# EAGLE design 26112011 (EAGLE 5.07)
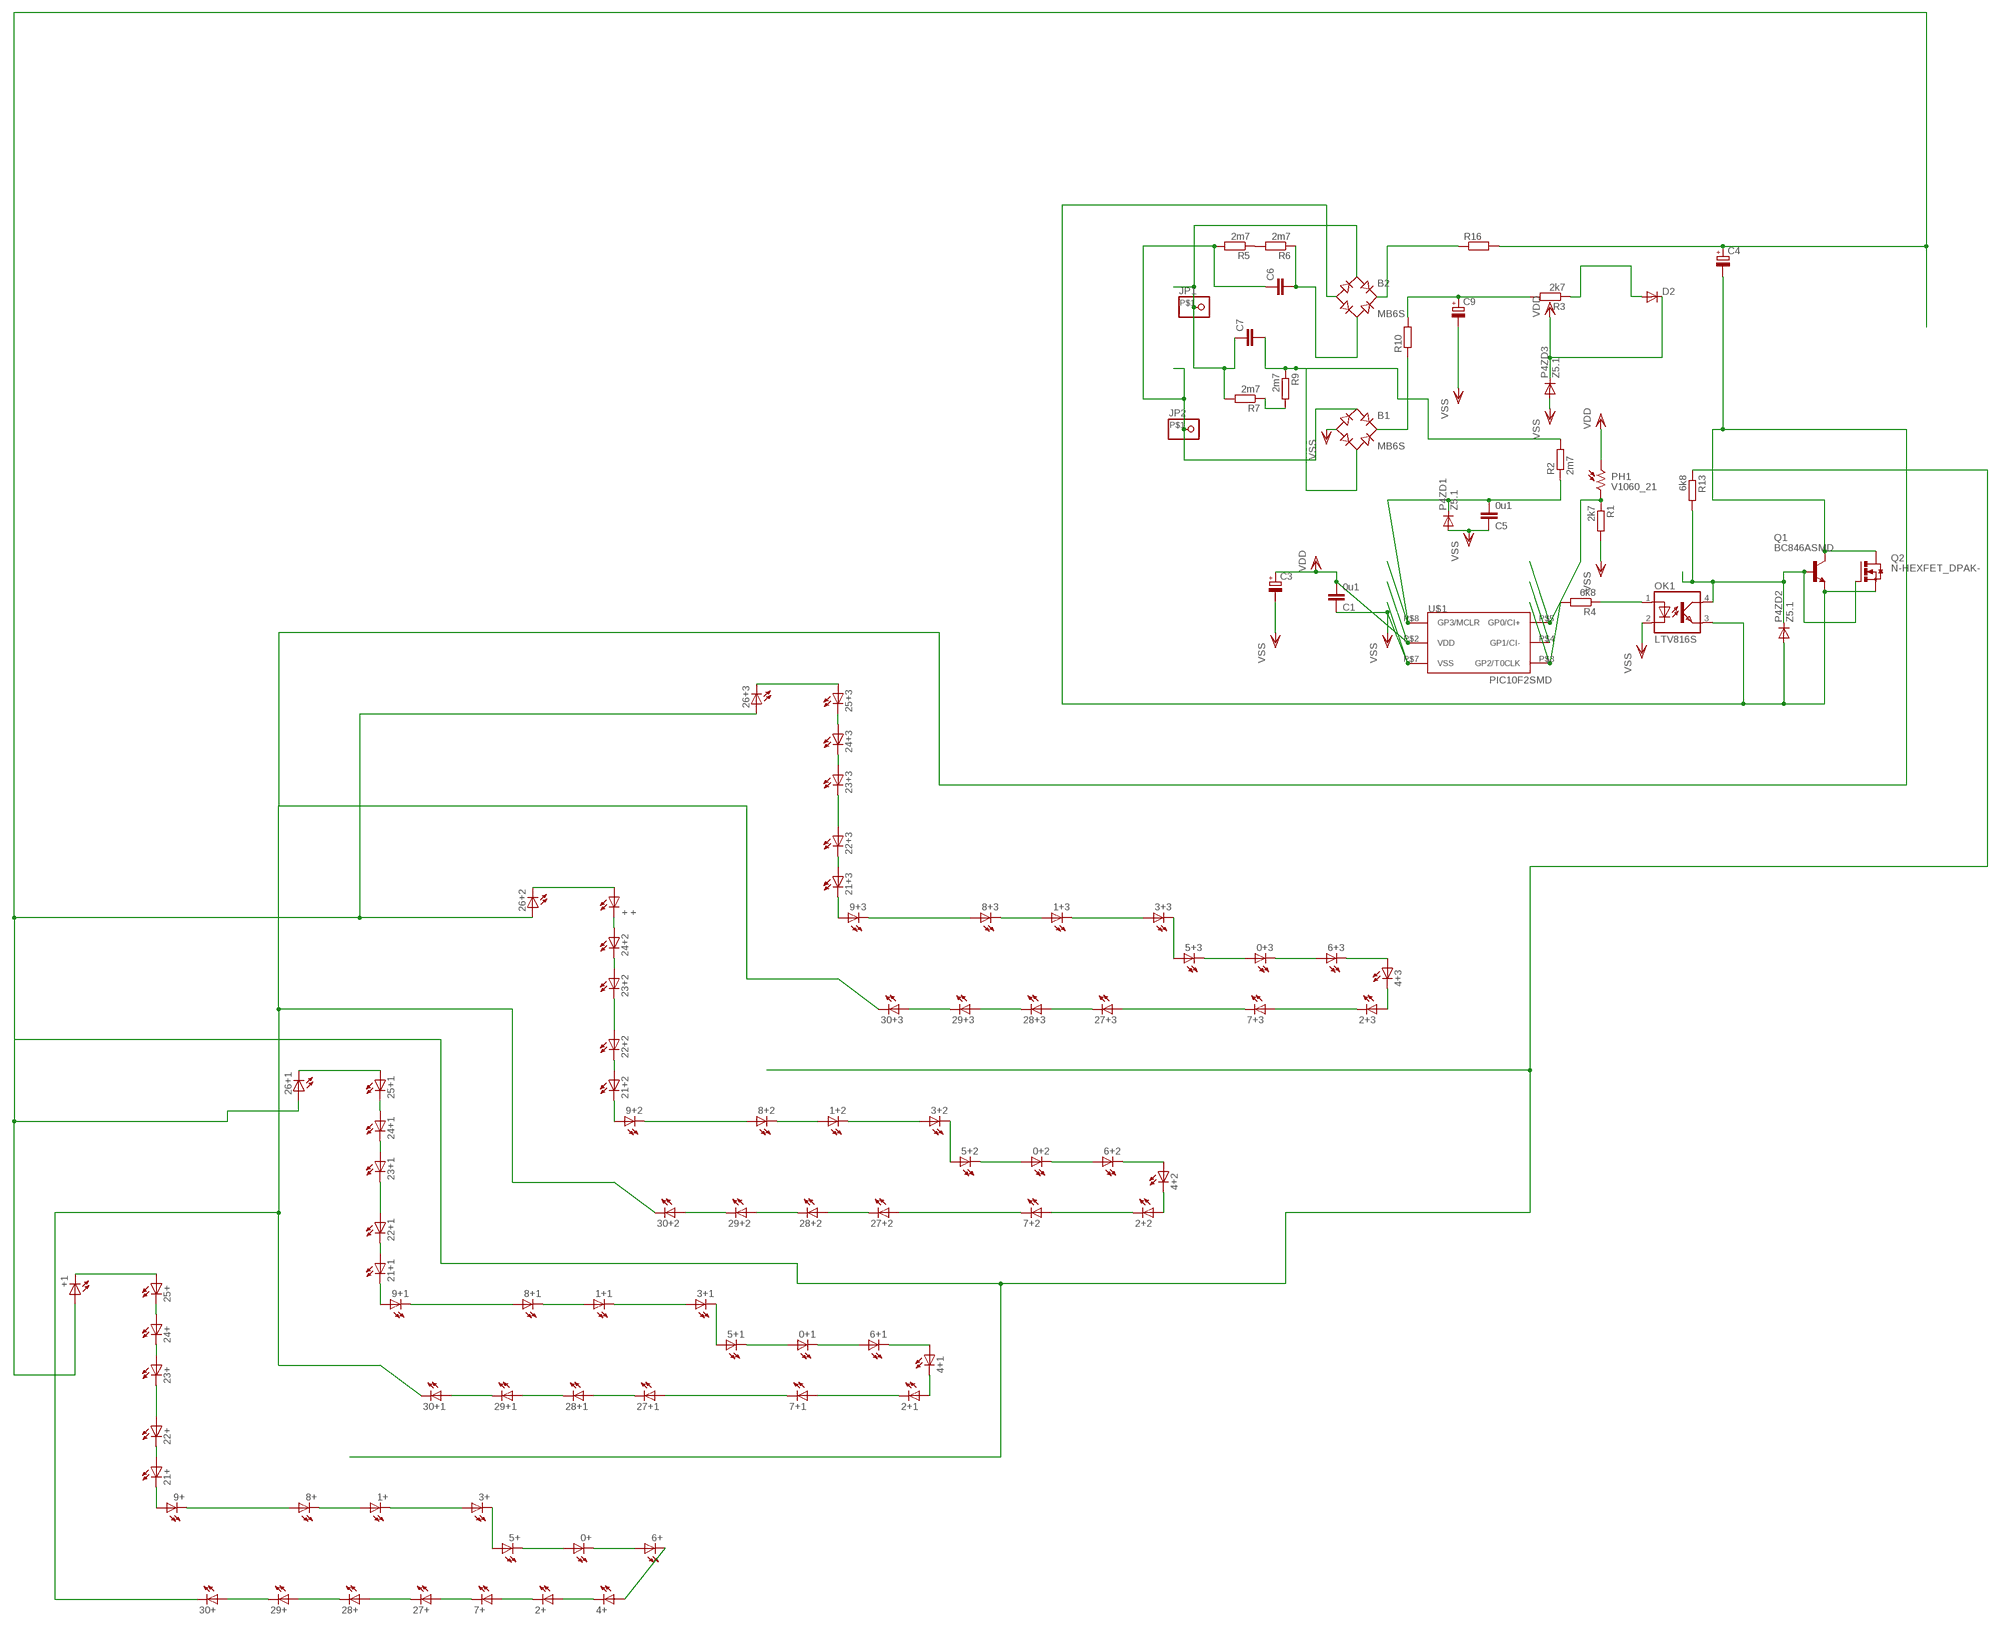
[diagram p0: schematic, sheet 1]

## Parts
0+  LED1210  [1210]
0+1  LED1210  [1210]
0+2  LED1210  [1210]
0+3  LED1210  [1210]
1+  LED1210  [1210]
1+1  LED1210  [1210]
1+2  LED1210  [1210]
1+3  LED1210  [1210]
2+  LED1210  [1210]
2+1  LED1210  [1210]
2+2  LED1210  [1210]
2+3  LED1210  [1210]
3+  LED1210  [1210]
3+1  LED1210  [1210]
3+2  LED1210  [1210]
3+3  LED1210  [1210]
4+  LED1210  [1210]
4+1  LED1210  [1210]
4+2  LED1210  [1210]
4+3  LED1210  [1210]
5+  LED1210  [1210]
5+1  LED1210  [1210]
5+2  LED1210  [1210]
5+3  LED1210  [1210]
6+  LED1210  [1210]
6+1  LED1210  [1210]
6+2  LED1210  [1210]
6+3  LED1210  [1210]
7+  LED1210  [1210]
7+1  LED1210  [1210]
7+2  LED1210  [1210]
7+3  LED1210  [1210]
8+  LED1210  [1210]
8+1  LED1210  [1210]
8+2  LED1210  [1210]
8+3  LED1210  [1210]
9+  LED1210  [1210]
9+1  LED1210  [1210]
9+2  LED1210  [1210]
9+3  LED1210  [1210]
21+  LED1210  [1210]
21+1  LED1210  [1210]
21+2  LED1210  [1210]
21+3  LED1210  [1210]
22+  LED1210  [1210]
22+1  LED1210  [1210]
22+2  LED1210  [1210]
22+3  LED1210  [1210]
23+  LED1210  [1210]
23+1  LED1210  [1210]
23+2  LED1210  [1210]
23+3  LED1210  [1210]
24+  LED1210  [1210]
24+1  LED1210  [1210]
24+2  LED1210  [1210]
24+3  LED1210  [1210]
25+  LED1210  [1210]
25+1  LED1210  [1210]
25+3  LED1210  [1210]
26+1  LED1210  [1210]
26+2  LED1210  [1210]
26+3  LED1210  [1210]
27+  LED1210  [1210]
27+1  LED1210  [1210]
27+2  LED1210  [1210]
27+3  LED1210  [1210]
28+  LED1210  [1210]
28+1  LED1210  [1210]
28+2  LED1210  [1210]
28+3  LED1210  [1210]
29+  LED1210  [1210]
29+1  LED1210  [1210]
29+2  LED1210  [1210]
29+3  LED1210  [1210]
30+  LED1210  [1210]
30+1  LED1210  [1210]
30+2  LED1210  [1210]
30+3  LED1210  [1210]
+  +  LED1210  [1210]
+1  LED1210  [1210]
B1  MB6S  [SOIC-4]
B2  MB6S  [SOIC-4]
C1  0u1  C-EUC1206  [C1206]
C3  CPOL-EUD  [PANASONIC_D]
C4  CPOL-EUSANYO_SMD_F12  [SANYO-OSCON_SMD_F12]
C5  0u1  C-EUC1206  [C1206]
C6  C-EUSMD200  [SMD200]
C7  C-EUSMD100  [SMD100]
C9  CPOL-EUD  [PANASONIC_D]
D2  DIODE-MINIMELF  [MINIMELF]
JP1  PINHD-1X1SMD  [SMD1X1]
JP2  PINHD-1X1SMD  [SMD1X1]
OK1  LTV816S  [SMD4]
P4ZD1  Z5.1  DIODE-MINIMELF  [MINIMELF]
P4ZD2  Z5.1  DIODE-MINIMELF  [MINIMELF]
P4ZD3  Z5.1  DIODE-MINIMELF  [MINIMELF]
PH1  V1060_21  [TO-5_V10]
Q1  BC846ASMD  [SOT23]
Q2  N-HEXFET_DPAK-  [TO252]
R1  2k7  R-EU_R1206  [R1206]
R2  2m7  R-EU_R1206  [R1206]
R3  2k7  R-EU_R1206  [R1206]
R4  6k8  R-EU_R1206  [R1206]
R5  2m7  R-EU_R1210  [R1210]
R6  2m7  R-EU_R1210  [R1210]
R7  2m7  R-EU_R1210  [R1210]
R9  2m7  R-EU_R1210  [R1210]
R10  R-EU_SMD15  [SMDCARB15]
R13  6k8  R-EU_R1206  [R1206]
R16  R-EU_SMD15  [SMDCARB15]
U$1  PIC10F2SMD  [DIL8SMD]

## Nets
AC1: B1.~1(AC1) C6.P$1 JP2.P$1 R5.2
AC2: B2.~1(AC1) C7.P$1 JP1.P$1 R7.2
CBIG: B2.~2(AC2) C6.P$2 R6.1
CSMALL: B1.~2(AC2) C7.P$2 R2.2 R9.1
D+: 26+1.P$1(A) 26+2.P$1(A) 26+3.P$1(A) +1.P$1(A) C4.+ R13.1 R16.P$2
DR+: C9.+ R3.2 R10.P$2
MINUS: 30+1.P$2(C) 30+2.P$2(C) 30+3.P$2(C) 30+.P$2(C) C4.- Q1.3(C) Q2.3(D)
N$6: 8+.P$1(A) 9+.P$2(C)
N$7: 29+.P$2(C) 30+.P$1(A)
N$8: 28+.P$2(C) 29+.P$1(A)
N$9: 27+.P$2(C) 28+.P$1(A)
N$10: 29+1.P$2(C) 30+1.P$1(A)
N$11: 28+1.P$2(C) 29+1.P$1(A)
N$12: 2+.P$2(C) 7+.P$1(A)
N$13: 7+.P$2(C) 27+.P$1(A)
N$14: 2+.P$1(A) 4+.P$2(C)
N$15: 4+.P$1(A) 6+.P$2(C)
N$16: 0+.P$2(C) 6+.P$1(A)
N$17: 0+.P$1(A) 5+.P$2(C)
N$18: 3+.P$2(C) 5+.P$1(A)
N$19: 1+.P$2(C) 3+.P$1(A)
N$20: 1+.P$1(A) 8+.P$2(C)
N$21: 27+1.P$2(C) 28+1.P$1(A)
N$22: 2+1.P$1(A) 4+1.P$2(C)
N$23: 9+.P$1(A) 21+.P$2(C)
N$24: 21+.P$1(A) 22+.P$2(C)
N$25: 22+.P$1(A) 23+.P$2(C)
N$26: 24+.P$1(A) 25+.P$2(C)
N$27: 25+.P$1(A) +1.P$2(C)
N$28: 23+.P$1(A) 24+.P$2(C)
N$29: 4+1.P$1(A) 6+1.P$2(C)
N$30: 0+1.P$2(C) 6+1.P$1(A)
N$31: 0+1.P$1(A) 5+1.P$2(C)
N$32: 3+1.P$2(C) 5+1.P$1(A)
N$33: 1+1.P$2(C) 3+1.P$1(A)
N$34: 1+1.P$1(A) 8+1.P$2(C)
N$35: 9+1.P$1(A) 21+1.P$2(C)
N$36: 21+1.P$1(A) 22+1.P$2(C)
N$37: 22+1.P$1(A) 23+1.P$2(C)
N$38: 25+1.P$1(A) 26+1.P$2(C)
N$39: 24+1.P$1(A) 25+1.P$2(C)
N$40: 23+1.P$1(A) 24+1.P$2(C)
N$41: 2+1.P$2(C) 7+1.P$1(A)
N$42: 7+1.P$2(C) 27+1.P$1(A)
N$43: 8+1.P$1(A) 9+1.P$2(C)
N$46: 29+2.P$2(C) 30+2.P$1(A)
N$47: 28+2.P$2(C) 29+2.P$1(A)
N$48: 27+2.P$2(C) 28+2.P$1(A)
N$49: 2+2.P$1(A) 4+2.P$2(C)
N$50: 4+2.P$1(A) 6+2.P$2(C)
N$51: 0+2.P$2(C) 6+2.P$1(A)
N$52: 0+2.P$1(A) 5+2.P$2(C)
N$53: 3+2.P$2(C) 5+2.P$1(A)
N$54: 1+2.P$2(C) 3+2.P$1(A)
N$55: 1+2.P$1(A) 8+2.P$2(C)
N$56: 9+2.P$1(A) 21+2.P$2(C)
N$57: 21+2.P$1(A) 22+2.P$2(C)
N$58: 22+2.P$1(A) 23+2.P$2(C)
N$59: 26+2.P$2(C) +.P$1(A)
N$60: 24+2.P$1(A) +.P$2(C)
N$61: 23+2.P$1(A) 24+2.P$2(C)
N$62: 2+2.P$2(C) 7+2.P$1(A)
N$63: 7+2.P$2(C) 27+2.P$1(A)
N$64: 8+2.P$1(A) 9+2.P$2(C)
N$67: 29+3.P$2(C) 30+3.P$1(A)
N$68: 28+3.P$2(C) 29+3.P$1(A)
N$69: 27+3.P$2(C) 28+3.P$1(A)
N$70: 2+3.P$1(A) 4+3.P$2(C)
N$71: 4+3.P$1(A) 6+3.P$2(C)
N$72: 0+3.P$2(C) 6+3.P$1(A)
N$73: 0+3.P$1(A) 5+3.P$2(C)
N$74: 3+3.P$2(C) 5+3.P$1(A)
N$75: 1+3.P$2(C) 3+3.P$1(A)
N$76: 1+3.P$1(A) 8+3.P$2(C)
N$77: 9+3.P$1(A) 21+3.P$2(C)
N$78: 21+3.P$1(A) 22+3.P$2(C)
N$79: 22+3.P$1(A) 23+3.P$2(C)
N$80: 25+3.P$1(A) 26+3.P$2(C)
N$81: 24+3.P$1(A) 25+3.P$2(C)
N$82: 23+3.P$1(A) 24+3.P$2(C)
N$83: 2+3.P$2(C) 7+3.P$1(A)
N$84: 7+3.P$2(C) 27+3.P$1(A)
N$85: 8+3.P$1(A) 9+3.P$2(C)
N$86: C5.2 P4ZD1.C R2.1 U$1.P$8(GP3/MCLR)
N$87: OK1.1(A) R4.1
N$88: PH1.2 R1.1 U$1.P$5(GP0/CI+)
N$89: R5.1 R6.2
N$90: R7.1 R9.2
N$91: B2.+ R16.P$1
N$92: D2.A R3.1
N$93: B2.- OK1.3(EMIT) P4ZD2.A Q1.2(E) Q2.2(S)
N$94: OK1.4(COL) P4ZD2.C Q1.1(B) Q2.1(G) R13.2
N$95: R4.2 U$1.P$3(GP2/T0CLK)
N$102: U$1.P$4(GP1/CI-)
RECDR+: B1.+ R10.P$1
VDD: C1.2 C3.+ D2.C P4ZD3.C PH1.1 U$1.P$2(VDD)
VSS: B1.- C1.1 C3.- C5.1 C9.- OK1.2(C) P4ZD1.A P4ZD3.A R1.2 U$1.P$7(VSS)

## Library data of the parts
0+ 0+1-0+3 1+ 1+1-1+3 2+ 2+1-2+3 3+ 3+1-3+3 4+ 4+1-4+3 5+ 5+1-5+3 6+ 6+1-6+3 7+ 7+1-7+3 8+ 8+1-8+3 9+ 9+1-9+3 21+ 21+1-21+3 22+ 22+1-22+3 23+ 23+1-23+3 24+ 24+1-24+3 25+ 25+1 25+3 26+1-26+3 27+ 27+1-27+3 28+ 28+1-28+3 29+ 29+1-29+3 30+ 30+1-30+3 + +1 = led(2):LED: LED
B1 B2 = rectifier:MB*S: Bridge Rectifier Source: http://www.fairchildsemi.com/ds/MB/MB6S.pdf
C1 C5-C7 = rcl:C-EU: CAPACITOR, European symbol
C3 C4 C9 = rcl-2:CPOL-EU: POLARIZED CAPACITOR, European symbol
D2 P4ZD1-P4ZD3 = diode:DIODE-: DIODE
JP1 JP2 = pinhead:PINHD-1X1: PIN HEADER
OK1 = optocoupler:LTV816: OPTO COUPLER Source: LITEON, LTV816.pdf
PH1 = photo-elements:?1060*: Sensor Street Light control
Q1 = transistor-npn:BC846*: NPN Transistor
Q2 = transistor-power:N-HEXFET_?-*: HEXFET® Power MOSFET
R1-R7 R9 R13 = rcl-2:R-EU_: RESISTOR, European symbol
R10 R16 = rcl:R-EU_: RESISTOR, European symbol
U$1 = microchip-5:PIC10F2*: uPC nW 0,25/0,5k Program Flash memory Comparator

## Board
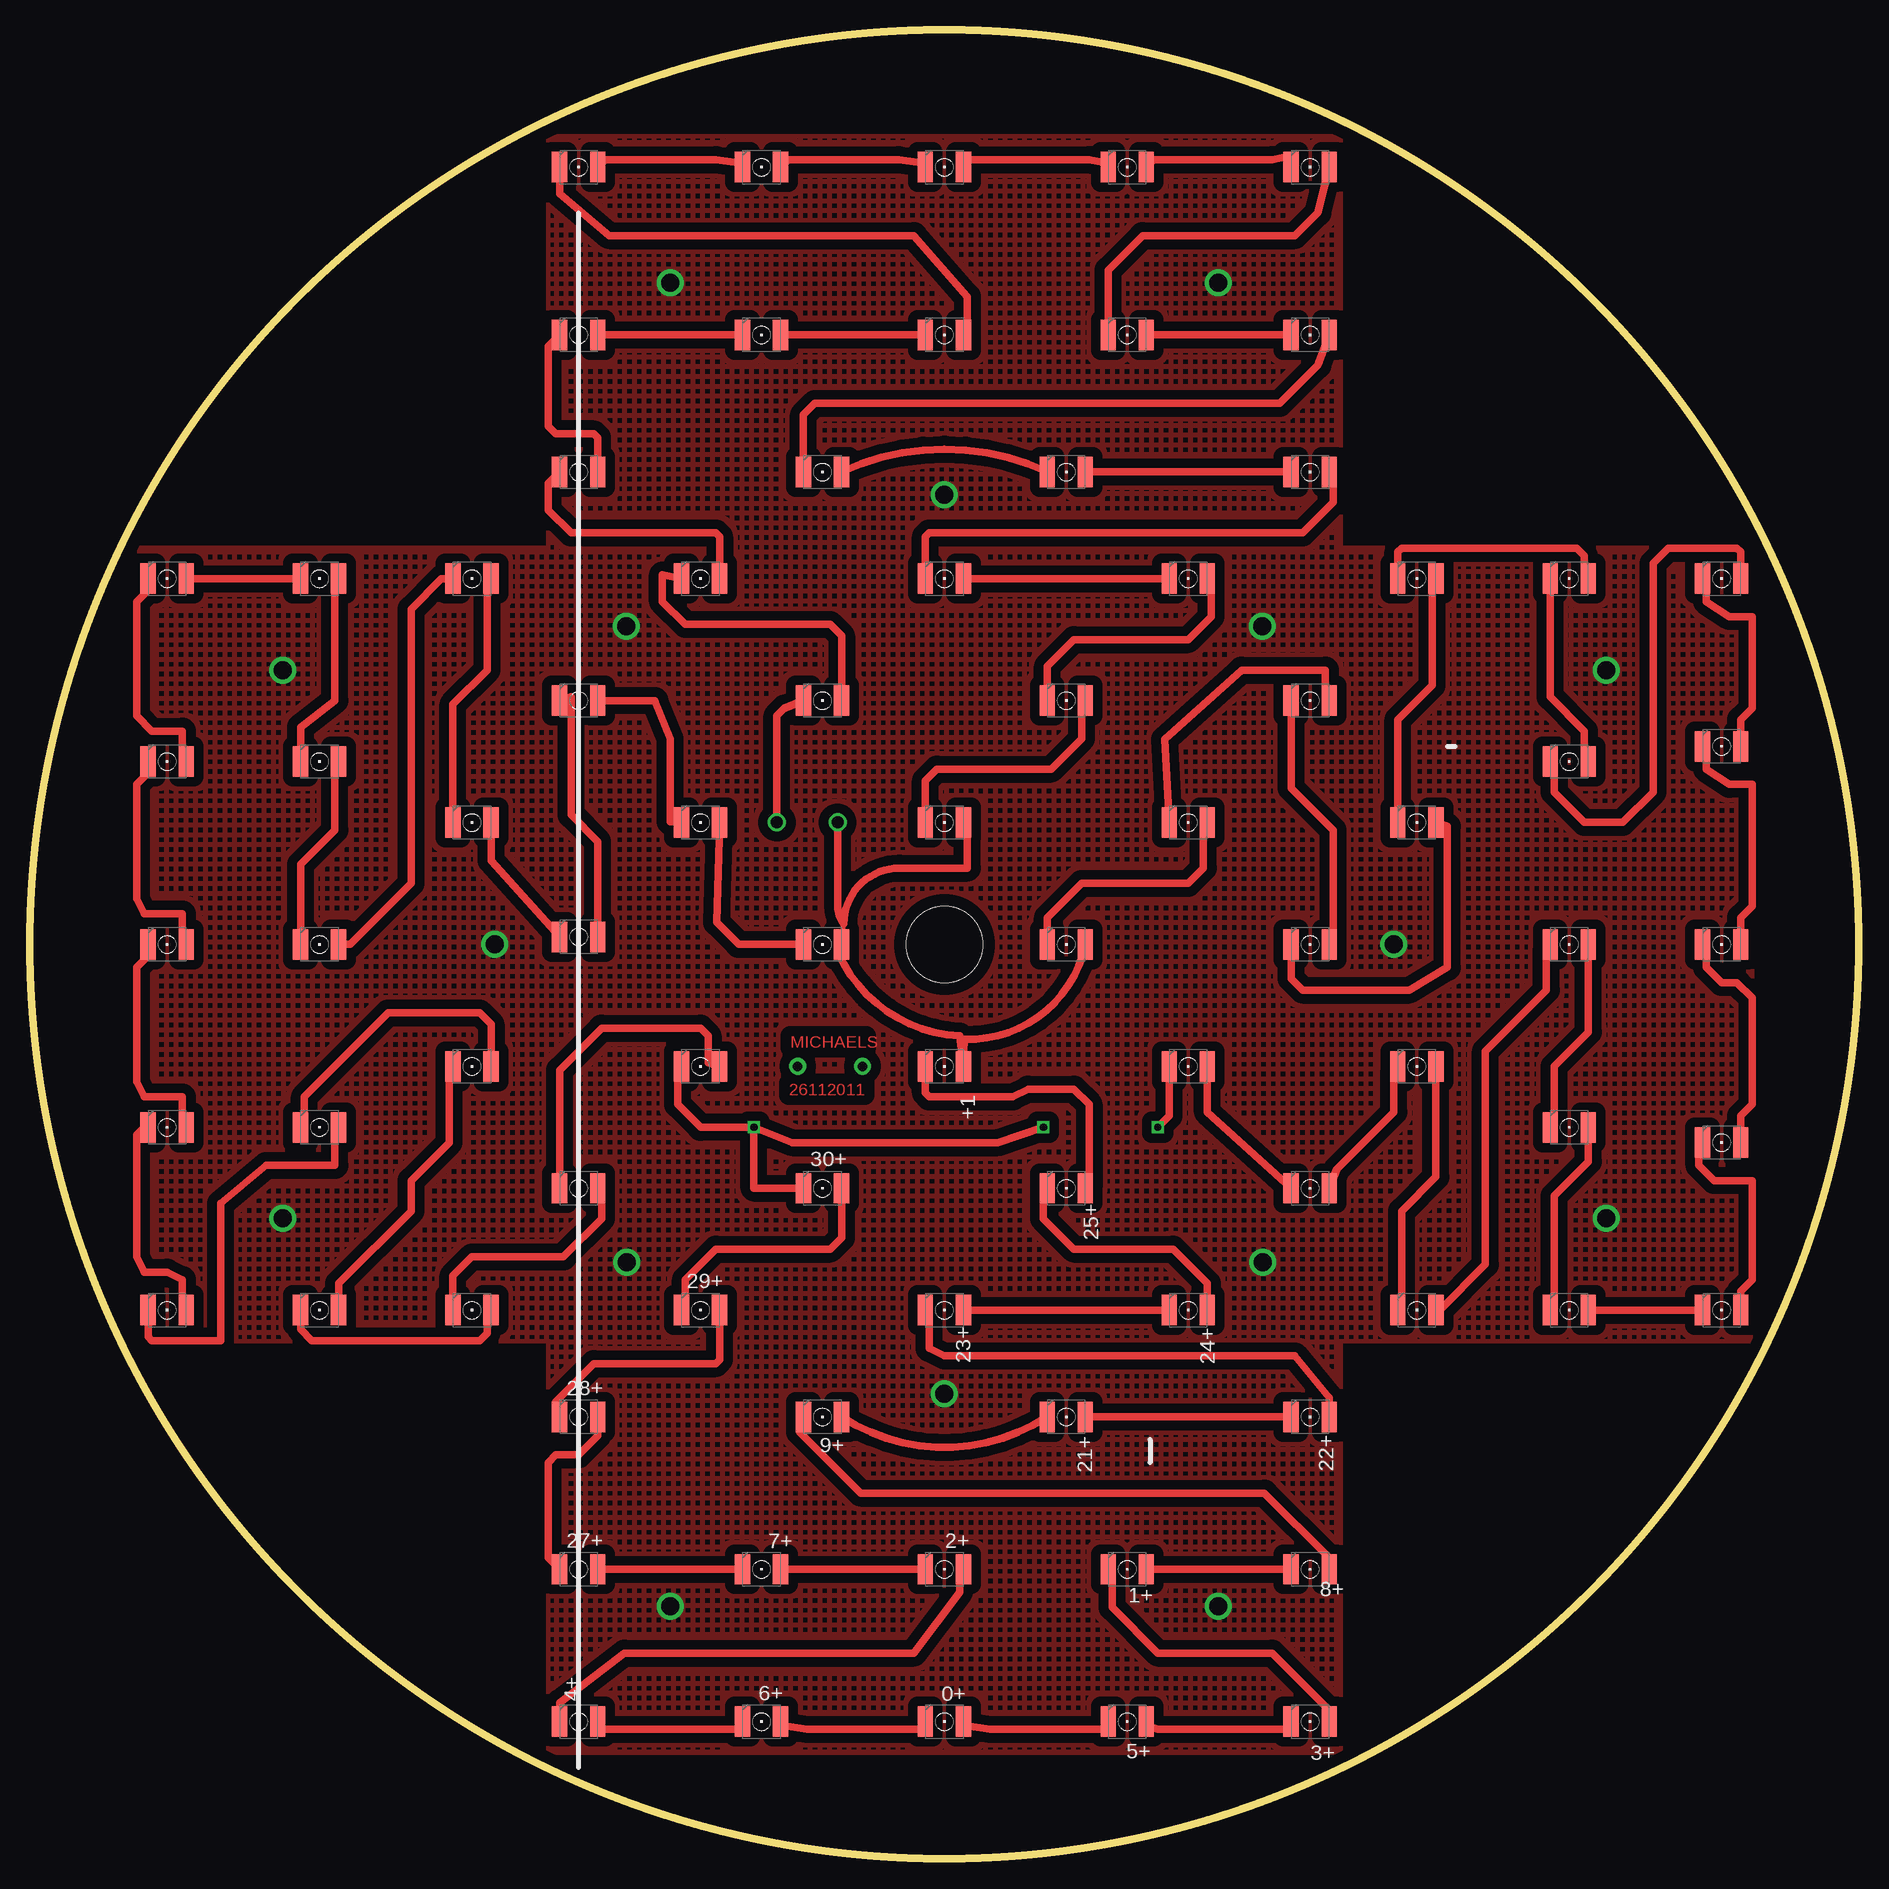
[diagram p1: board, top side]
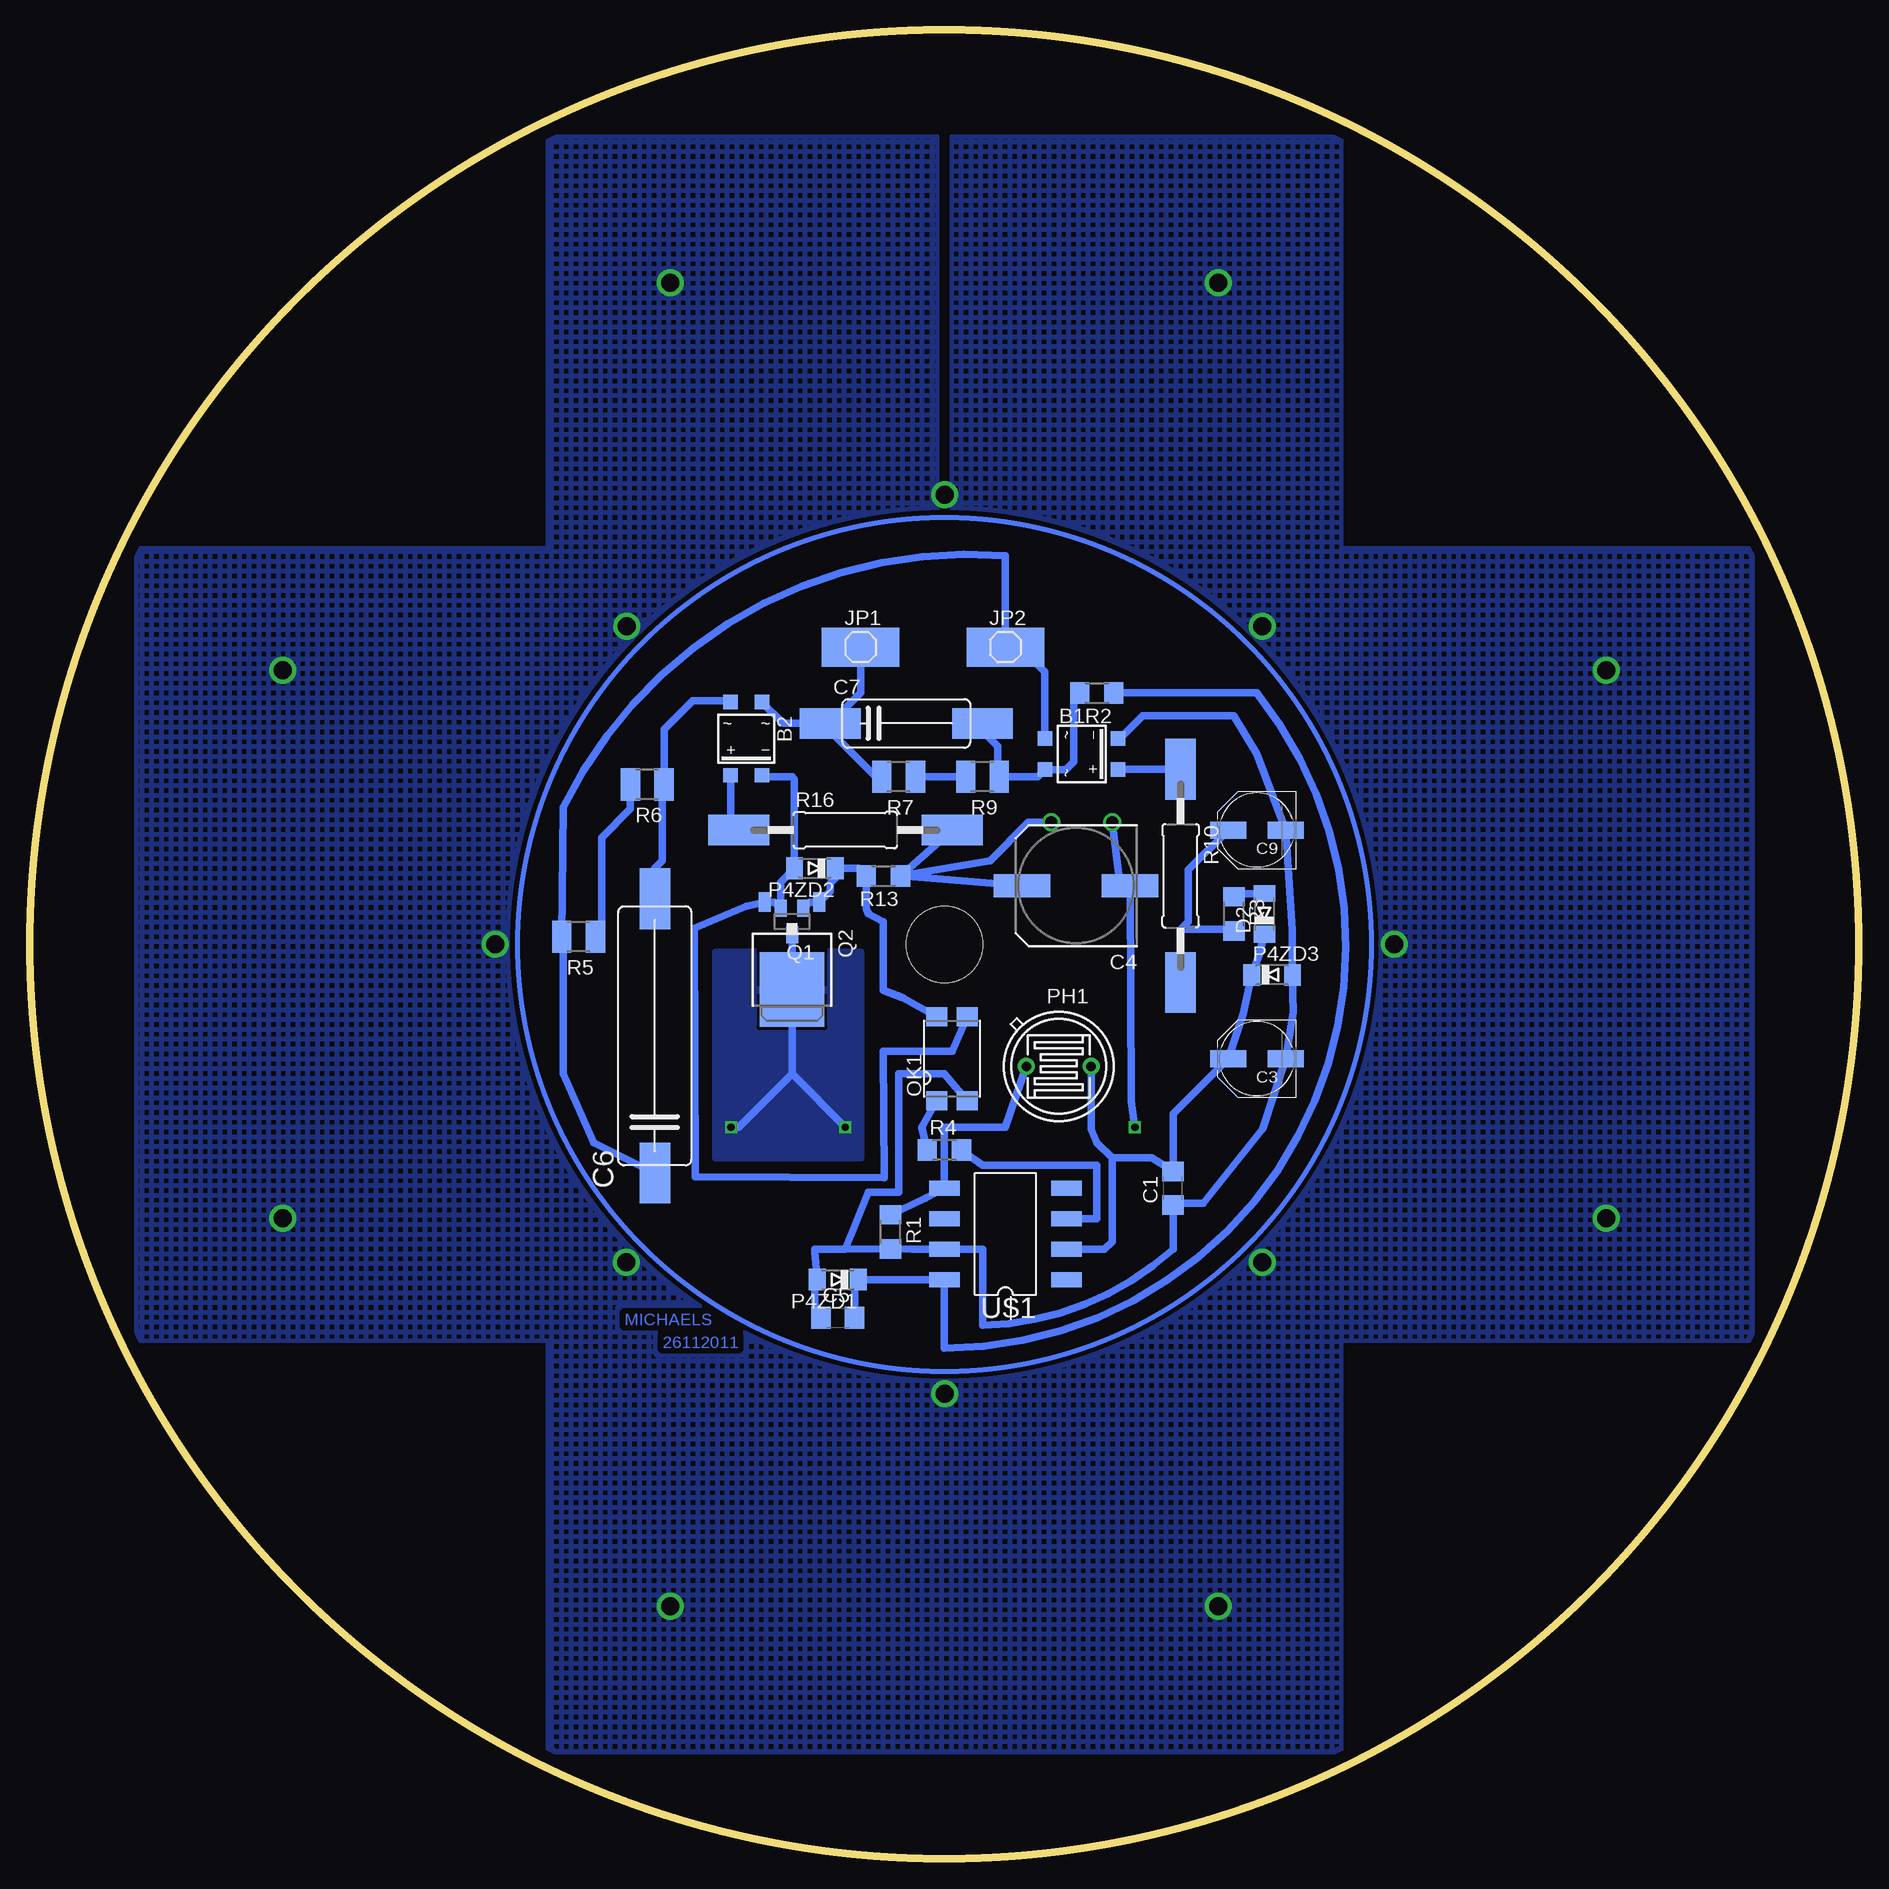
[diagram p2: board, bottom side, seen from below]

Size 152.4 x 152.4 mm. Coordinates in mm from the lower left corner, seen from the top.
Outline: circle at 76.2,76.2 radius 76.2
Copper layers (1*16): Top 0.035mm / dielectric 1.5mm / Bottom 0.035mm
Design rules "default": minimum track width 10mil, minimum drill 24mil, track to track 8mil, track to pad 8mil, pad to pad 8mil, via to via 8mil, smd to smd 8mil, copper to edge 40mil, drill to drill 8mil, minimum pad ring 10mil, minimum via ring 8mil, stop-mask expansion 4mil, vias tented up to drill 0mil, thermal gap 10mil
Holes 6.35 mm at 76.2,76.2

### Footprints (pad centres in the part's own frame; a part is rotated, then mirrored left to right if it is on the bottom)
1210 = smd 1.27 x 2.54: P$1 1.587,0; P$2 -1.587,0
SOIC-4 = smd 1.2 x 1.2: + 1.3,3.05; - -1.3,3.05; ~1 -1.3,-3.05; ~2 1.3,-3.05
C1206 = smd 1.6 x 1.8: 1 -1.4,0; 2 1.4,0
PANASONIC_D = smd 3 x 1.4: + 2.4,0; - -2.4,0
SANYO-OSCON_SMD_F12 = smd 4.7 x 1.9: + 4.5,0; - -4.5,0
SMD200 = smd 5.08 x 2.54: P$1 -10.16,0; P$2 12.7,0
SMD100 = smd 5.08 x 2.54: P$1 -6.35,0; P$2 6.35,0
MINIMELF = smd 1.4 x 1.8: A 1.7,0; C -1.7,0
SMD1X1 = smd 6.452 x 3.251: P$1 0,0
SMD4 = smd 1.78 x 1.55: 1 -1.27,-3.5; 2 1.27,-3.5; 3 1.27,3.5; 4 -1.27,3.5
TO-5_V10 = drill 0.8 pad 1.4 round: 1 -2.7,0; 2 2.7,0
SOT23 = smd 1 x 1.4: 1 -0.95,-1.1; 2 0.95,-1.1; 3 0,1.1
TO252 = smd 1 x 1.6: 1 -2.28,-3.53; 2 2.28,-3.53 | smd 5.4 x 6.2: 3 0,3.77
R1206 = smd 1.6 x 1.803: 1 -1.422,0; 2 1.422,0
R1210 = smd 1.6 x 2.7: 1 -1.4,0; 2 1.4,0
SMDCARB15 = smd 5.08 x 2.54: P$1 -8.89,0; P$2 8.89,0
DIL8SMD = smd 1.27 x 2.54: P$1 -3.81,-5.08; P$2 -1.27,-5.08; P$3 1.27,-5.08; P$4 3.81,-5.08; P$5 3.81,5.08; P$6 1.27,5.08; P$7 -1.27,5.08; P$8 -3.81,5.08

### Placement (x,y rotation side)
0+  76.2,11.43 0 top
0+1  140.97,59.69 0 top
0+2  76.2,140.97 0 top
0+3  11.43,76.2 0 top
1+  91.44,24.13 0 top
1+1  140.97,106.68 0 top
1+2  91.44,127 0 top
1+3  24.13,106.68 0 top
2+  76.2,24.13 0 top
2+1  128.27,60.96 0 top
2+2  76.2,127 0 top
2+3  24.13,60.96 0 top
3+  106.68,11.43 0 top
3+1  140.97,92.71 0 top
3+2  106.68,140.97 0 top
3+3  11.43,106.68 0 top
4+  45.72,11.43 0 top
4+1  128.27,45.72 0 top
4+2  45.72,140.97 0 top
4+3  11.43,45.72 0 top
5+  91.44,11.43 0 top
5+1  140.97,76.2 0 top
5+2  91.44,140.97 0 top
5+3  11.43,91.44 0 top
6+  60.96,11.43 0 top
6+1  140.97,45.72 0 top
6+2  60.96,140.97 0 top
6+3  11.43,60.96 0 top
7+  60.96,24.13 0 top
7+1  128.27,76.2 0 top
7+2  60.96,127 0 top
7+3  36.83,66.04 0 top
8+  106.68,24.13 0 top
8+1  128.27,91.44 0 top
8+2  106.68,127 0 top
8+3  24.13,91.44 0 top
9+  66.04,36.83 0 top
9+1  128.27,106.68 0 top
9+2  66.04,115.57 0 top
9+3  24.13,76.2 0 top
21+  86.36,36.83 0 top
21+1  115.57,106.68 0 top
21+2  86.36,115.57 0 top
21+3  36.83,106.68 0 top
22+  106.68,36.83 0 top
22+1  115.57,86.36 0 top
22+2  106.68,115.57 0 top
22+3  36.83,86.36 0 top
23+  76.2,45.72 0 top
23+1  106.68,76.2 0 top
23+2  76.2,106.68 0 top
23+3  45.72,76.83 0 top
24+  96.52,45.72 0 top
24+1  106.68,96.52 0 top
24+2  96.52,106.68 0 top
24+3  45.72,96.52 0 top
25+  86.36,55.88 0 top
25+1  96.52,86.36 0 top
25+3  55.88,86.36 0 top
26+1  86.36,76.2 0 top
26+2  76.2,86.36 0 top
26+3  66.04,76.2 0 top
27+  45.72,24.13 0 top
27+1  115.57,45.72 0 top
27+2  45.72,127 0 top
27+3  24.13,45.72 0 top
28+  45.72,36.83 0 top
28+1  115.57,66.04 0 top
28+2  45.72,115.57 0 top
28+3  36.83,45.72 0 top
29+  55.88,45.72 0 top
29+1  106.68,55.88 0 top
29+2  55.88,106.68 0 top
29+3  45.72,55.88 0 top
30+  66.04,55.88 0 top
30+1  96.52,66.04 0 top
30+2  66.04,96.52 0 top
30+3  55.88,66.04 0 top
+  86.36,96.52 0 top
+1  76.2,66.04 0 top
B1  64.77,92.08 270 bottom
B2  92.71,93.34 180 bottom
C1  57.15,55.88 90 bottom
C3  50.16,66.67 180 bottom
C4  65.22,81.09 180 bottom
C5  85.09,45.09 0 bottom
C6  100.33,67.31 90 bottom
C7  79.38,94.61 0 bottom
C9  50.16,85.72 180 bottom
D2  49.53,78.74 90 bottom
JP1  83.19,100.97 0 bottom
JP2  71.12,100.97 0 bottom
OK1  75.56,66.67 0 bottom
P4ZD1  85.09,48.26 180 bottom
P4ZD2  87,82.55 180 bottom
P4ZD3  48.9,73.66 0 bottom
PH1  66.67,66.04 180 bottom
Q1  88.9,78.11 180 bottom
Q2  88.9,76.2 180 bottom
R1  80.69,52.24 270 bottom
R2  63.5,97.16 180 bottom
R3  52.07,78.74 270 bottom
R4  76.2,59.05 0 bottom
R5  106.68,76.83 180 bottom
R6  100.97,89.53 180 bottom
R7  80.01,90.17 180 bottom
R9  73.03,90.17 180 bottom
R10  56.52,81.92 270 bottom
R13  81.28,81.92 180 bottom
R16  84.45,85.72 0 bottom
U$1  71.12,52.07 90 bottom

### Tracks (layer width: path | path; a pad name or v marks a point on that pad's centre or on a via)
AC1
  Bottom 0.61: B1.~1 67.82,98.94 69.85,100.97 JP2.P$1 71.12,108.58 arc-69 107.95,87.63 R5.2 107.95,76.7 107.95,65.41 105.41,59.69 C6.P$1
AC2
  Bottom 0.61: R7.2 81.92,90.17 86.36,94.61 C7.P$1 | JP1.P$1 83.19,97.16 C7.P$1 | C7.P$1 89.63,94.61 B2.~1
CBIG
  Bottom 0.61: B2.~2 94.14,96.52 97.16,96.52 99.56,94.11 R6.1 99.69,89.41 99.69,83.19 100.33,82.55 C6.P$2
CSMALL
  Bottom 0.61: R2.2 65.41,96.67 65.41,91.44 66.07,90.78 B1.~2 68.42,90.17 R9.1 71.75,90.3 71.75,92.71 73.03,93.98 C7.P$2
D+  (via drill 1 pad 1.27)
  Top 0.406: 67.81,77.92 26+3.P$1 67.31,75.56
  Top 0.61: 67.31,75.56 arc63 77.47,68.58 +1.P$1 77.86,68.3 arc80 26+1.P$1 | 26+2.P$1 78.11,86.04 78.11,82.55 72.44,82.55 arc90 67.81,77.92 arc-38 67.31,79.38 v67.31,86.36
  Bottom 0.61: R13.1 C4.+ | R13.1 R16.P$2 | v67.31,86.36 69.22,86.36 72.39,83.19 R13.1
DR+
  Bottom 0.61: C9.+ 55.88,82.41 55.88,78.11 56.52,77.47 | R10.P$2 56.52,77.47 | R3.2 52.22,77.47 56.52,77.47
MINUS  (via drill 0.6, 1 pad 1.27)
  Top 0.61: v60.33,60.96 63.5,59.69 80.64,59.69 v84.45,60.96 | 30+1.P$2 94.93,61.91 v93.98,60.96 | v60.33,60.96 55.88,60.96 53.98,62.87 53.98,65.72 30+3.P$2 | v60.33,60.96 60.33,55.88 30+.P$2 | v62.23,86.36 62.23,95.25 62.87,95.89 30+2.P$2
  Bottom 0.61: Q1.3 Q2.3 88.9,65.41 | v62.23,86.36 61.59,81.33 C4.- 60.63,63.11 v60.33,60.96 | v84.45,60.96 88.9,65.41 | v93.98,60.96 93.34,60.96 88.9,65.41
  pour Bottom: 83.82,75.56 95.25,75.56 95.25,74.3 95.25,58.42 83.19,58.42 83.19,75.56
N$6
  Top 0.61: 8+.P$1 108.27,25.08 102.87,30.48 69.22,30.48 64.14,35.56 64.14,36.51 9+.P$2
N$7
  Top 0.61: 30+.P$1 67.63,51.75 66.67,50.8 57.15,50.8 54.61,48.26 54.61,46.04 29+.P$2
N$8
  Top 0.61: 29+.P$1 57.47,41.59 57.15,41.27 46.99,41.27 43.81,38.1 43.81,37.15 28+.P$2
N$9
  Top 0.61: 28+.P$1 47.31,35.24 45.72,33.66 43.81,33.66 43.18,33.02 43.18,25.08 27+.P$2
N$10
  Top 0.61: 30+1.P$1 98.11,62.23 29+1.P$2
N$11
  Top 0.61: 29+1.P$1 108.9,57.47 113.67,62.23 113.67,65.72 28+1.P$2
N$12
  Top 0.61: 7+.P$1 2+.P$2
N$13
  Top 0.61: 27+.P$1 7+.P$2
N$14
  Top 0.61: 4+.P$2 44.13,13.02 49.53,17.14 73.66,17.14 77.47,22.23 77.47,23.81 2+.P$1
N$15
  Top 0.61: 4+.P$1 47.62,11.43 47.62,10.79 59.05,10.79 59.05,11.11 6+.P$2
N$16
  Top 0.61: 6+.P$1 62.55,11.11 64.77,10.79 74.93,10.79 74.93,11.11 0+.P$2
N$17
  Top 0.61: 0+.P$1 77.79,11.11 80.01,10.79 90.17,10.79 90.17,11.11 5+.P$2
N$18
  Top 0.61: 5+.P$1 93.03,11.11 93.98,10.79 105.41,10.79 105.41,11.11 3+.P$2
N$19
  Top 0.61: 3+.P$1 108.27,12.38 103.5,17.14 93.98,17.14 90.17,20.95 90.17,23.81 1+.P$2
N$20
  Top 0.61: 1+.P$1 8+.P$2
N$21
  Top 0.61: 28+1.P$1 117.16,56.83 114.3,53.98 114.3,46.04 27+1.P$2
N$22
  Top 0.61: 2+1.P$1 129.86,58.1 127,55.24 127,45.72 4+1.P$2
N$23
  Top 0.61: 9+.P$1 arc66 21+.P$2
N$24
  Top 0.61: 21+.P$1 22+.P$2
N$25
  Top 0.61: 22+.P$1 108.27,38.42 105.41,41.91 76.2,41.91 74.93,42.55 74.93,44.77 23+.P$2
N$26
  Top 0.61: 24+.P$1 98.11,47.94 95.25,50.8 87,50.8 84.45,53.34 84.45,55.31 25+.P$2
N$27
  Top 0.61: +1.P$2 74.61,63.82 74.93,63.5 81.92,63.5 83.19,64.14 87,64.14 88.27,62.87 88.27,55.94 25+.P$1
N$28
  Top 0.61: 23+.P$1 24+.P$2
N$29
  Top 0.61: 4+1.P$1 6+1.P$2
N$30
  Top 0.61: 6+1.P$1 142.56,47.31 143.51,48.26 143.51,56.52 140.34,56.52 139.06,57.78 139.06,59.37 0+1.P$2
N$31
  Top 0.61: 0+1.P$1 142.56,61.91 143.51,62.87 143.51,71.75 142.24,73.03 140.97,73.03 139.7,74.3 139.7,75.88 5+1.P$2
N$32
  Top 0.61: 5+1.P$1 142.56,78.42 143.51,79.38 143.51,89.53 141.6,89.53 139.7,90.81 139.7,92.39 3+1.P$2
N$33
  Top 0.61: 3+1.P$1 142.56,94.93 143.51,95.89 143.51,103.5 141.6,103.5 139.7,104.78 139.7,106.36 1+1.P$2
N$34
  Top 0.61: 1+1.P$1 142.56,108.9 142.24,109.22 136.53,109.22 135.25,107.95 135.25,88.9 132.72,86.36 129.54,86.36 127,88.9 127,91.12 8+1.P$2
N$35
  Top 0.61: 21+1.P$2 113.98,108.9 114.3,109.22 128.91,109.22 129.54,108.58 129.54,107 9+1.P$1
N$36
  Top 0.61: 22+1.P$2 113.98,94.93 116.84,97.79 116.84,106.36 21+1.P$1
N$37
  Top 0.61: 23+1.P$2 105.09,73.34 106.05,72.39 114.94,72.39 118.11,74.3 118.11,86.04 22+1.P$1
N$38
  Top 0.61: 26+1.P$2 84.77,78.42 87.63,81.28 96.52,81.28 97.79,82.55 97.79,85.03 25+1.P$1
N$39
  Top 0.61: 25+1.P$2 94.55,93.28 100.97,99.06 107.95,99.06 107.95,96.84 24+1.P$1
N$40
  Top 0.61: 24+1.P$2 105.09,89.22 108.58,85.72 108.58,76.52 23+1.P$1
N$41
  Top 0.61: 7+1.P$1 129.86,68.9 127,66.04 127,61.28 2+1.P$2
N$42
  Top 0.61: 27+1.P$1 117.47,45.72 121.28,49.53 121.28,67.31 126.36,72.39 126.36,75.88 7+1.P$2
N$43
  Top 0.61: 9+1.P$2 126.68,96.84 129.54,93.98 129.54,91.76 8+1.P$1
N$46
  Top 0.61: 30+2.P$1 67.63,101.92 66.67,102.87 54.61,102.87 52.7,104.78 52.7,107 29+2.P$2
N$47
  Top 0.61: 29+2.P$1 57.47,110.17 57.15,110.49 45.09,110.49 43.18,112.39 43.18,114.62 28+2.P$2
N$48
  Top 0.61: 28+2.P$1 47.31,118.43 46.99,118.75 43.81,118.75 43.18,119.38 43.18,126.05 27+2.P$2
N$49
  Top 0.61: 4+2.P$2 44.13,138.75 48.26,135.25 73.66,135.25 78.11,130.18 78.11,127.32 2+2.P$1
N$50
  Top 0.61: 6+2.P$2 59.37,141.29 57.15,141.6 47.94,141.6 4+2.P$1
N$51
  Top 0.61: 0+2.P$2 74.61,141.29 72.39,141.6 63.18,141.6 6+2.P$1
N$52
  Top 0.61: 5+2.P$2 89.85,141.29 88.27,141.6 78.11,141.6 78.11,141.29 0+2.P$1
N$53
  Top 0.61: 3+2.P$2 105.09,141.92 103.5,141.6 93.66,141.6 5+2.P$1
N$54
  Top 0.61: 1+2.P$2 89.85,132.4 92.71,135.25 105.41,135.25 107.31,137.16 3+2.P$1 107.95,140.65
N$55
  Top 0.61: 1+2.P$1 8+2.P$2
N$56
  Top 0.61: 9+2.P$1 arc-50 21+2.P$2
N$57
  Top 0.61: 21+2.P$1 22+2.P$2
N$58
  Top 0.61: 23+2.P$2 74.61,110.17 74.93,110.49 106.05,110.49 108.58,113.03 108.58,115.25 22+2.P$1
N$59
  Top 0.61: 26+2.P$2 74.61,89.85 75.56,90.81 85.09,90.81 87.63,93.34 87.63,96.2 +.P$1
N$60
  Top 0.61: +.P$2 84.77,99.38 87,101.6 96.52,101.6 98.42,103.5 98.42,106.36 24+2.P$1
N$61
  Top 0.61: 23+2.P$1 24+2.P$2
N$62
  Top 0.61: 7+2.P$1 2+2.P$2
N$63
  Top 0.61: 27+2.P$1 7+2.P$2
N$64
  Top 0.61: 9+2.P$2 64.45,120.33 65.41,121.28 104.14,121.28 107.31,124.46 8+2.P$1 108.58,127.32
N$67
  Top 0.61: 29+3.P$2 44.13,65.72 47.62,69.22 55.88,69.22 56.52,68.58 56.52,66.36 30+3.P$1
N$68
  Top 0.61: 28+3.P$2 35.24,48.58 36.83,50.16 44.45,50.16 47.62,53.34 47.62,54.93 29+3.P$1
N$69
  Top 0.61: 27+3.P$2 22.54,44.13 23.5,43.18 37.47,43.18 38.1,43.81 38.1,45.4 28+3.P$1
N$70
  Top 0.61: 4+3.P$2 9.84,43.5 10.16,43.18 15.88,43.18 15.88,54.61 19.68,57.78 25.4,57.78 25.4,60.64 2+3.P$1
N$71
  Top 0.61: 6+3.P$2 9.53,60.96 8.89,60.33 8.89,50.16 9.53,48.9 11.43,48.9 12.7,48.26 12.7,46.04 4+3.P$1
N$72
  Top 0.61: 0+3.P$2 9.84,75.25 8.89,74.3 8.89,64.77 9.53,63.5 12.7,63.5 12.7,61.28 6+3.P$1
N$73
  Top 0.61: 5+3.P$2 9.84,90.49 8.89,89.53 8.89,80.01 9.53,78.74 12.7,78.74 12.7,76.52 0+3.P$1
N$74
  Top 0.61: 3+3.P$2 9.84,105.73 8.89,104.78 8.89,95.25 10.16,93.98 12.7,93.98 12.7,91.76 5+3.P$1
N$75
  Top 0.61: 3+3.P$1 1+3.P$2
N$76
  Top 0.61: 8+3.P$2 22.54,94.3 25.4,96.52 25.4,106.36 1+3.P$1
N$77
  Top 0.61: 21+3.P$2 34.29,106.68 31.75,104.14 31.75,81.28 26.67,76.2 9+3.P$1
N$78
  Top 0.61: 22+3.P$2 35.24,96.2 38.1,99.06 38.1,106.36 21+3.P$1
N$79
  Top 0.61: 22+3.P$1 38.42,83.19 23+3.P$2
N$80
  Top 0.61: 25+3.P$1 57.21,78.04 59.05,76.2 26+3.P$2
N$81
  Top 0.61: 24+3.P$1 52.07,96.52 53.34,93.34 53.34,86.42 25+3.P$2
N$82
  Top 0.61: 23+3.P$1 47.31,84.77 45.09,87 45.09,96.84 24+3.P$2
N$83
  Top 0.61: 7+3.P$1 38.42,69.53 37.47,70.48 29.84,70.48 22.86,63.5 22.86,61.28 2+3.P$2
N$84
  Top 0.61: 27+3.P$1 25.72,47.94 31.75,53.98 31.75,56.52 34.92,59.69 34.92,65.72 7+3.P$2
N$85
  Top 0.61: 9+3.P$2 22.54,82.87 25.4,85.72 25.4,91.12 8+3.P$1
N$86
  Bottom 0.61: R2.1 50.16,97.16 arc129 76.2,42.55 U$1.P$8 P4ZD1.C 83.69,47.96 C5.2
N$87
  Bottom 0.61: OK1.1 78.11,60.96 R4.1
N$88
  Bottom 0.61: R1.1 77.81,55.06 U$1.P$5 76.2,60.96 71.12,60.96 PH1.2
N$89
  Bottom 0.61: R5.1 104.78,77.34 104.78,85.09 102.36,87.5 R6.2
N$90
  Bottom 0.61: R9.2 R7.1
N$91
  Bottom 0.61: B2.+ 94.01,86.39 R16.P$1
N$92
  Bottom 0.61: R3.1 51.79,80.44 D2.A
N$93
  Bottom 0.61: OK1.3 75.56,67.31 81.28,67.31 81.22,56.77 96.97,56.84 97.03,77.54 92.71,79.38 Q2.2 90.38,79.73 Q1.2 89.85,81.39 P4ZD2.A 88.69,89.97 88.9,90.17 91.28,90.17 B2.-
N$94
  Bottom 0.61: OK1.4 79.69,71.75 81.28,72.39 81.28,78.11 82.55,78.74 82.7,79.22 R13.2 83.34,82.55 P4ZD2.C 85.3,81.71 85.72,81.28 85.72,80.62 Q2.1 87.42,79.73 Q1.1
N$95
  Bottom 0.61: U$1.P$3 63.5,53.34 63.5,57.78 73.03,57.78 R4.2
RECDR+
  Bottom 0.61: B1.+ 61.69,90.81 R10.P$1
SINK  (via drill 1.5)
  other vias: 102.71,49.72 76.19,38.74 49.72,49.72 113.65,76.21 102.68,102.73 76.19,113.67 49.7,102.71 38.73,76.2 99.03,131.34 53.37,21.06 131.34,53.37 131.34,99.03 21.06,53.37 53.37,131.34 99.03,21.06 21.06,99.03
  pour Bottom (isolate 0.406, hatched): 75.56,143.51 43.18,143.51 43.18,109.22 8.89,109.22 8.89,43.18 43.18,43.18 43.18,8.89 109.22,8.89 109.22,43.18 143.51,43.18 143.51,109.22 109.22,109.22 109.22,143.51 76.83,143.51 76.83,111.76 arc-57 104.14,98.42 arc-48 111.76,76.83 arc-40 105.41,55.88 arc-44 89.53,43.18 arc-54 62.87,43.18 arc-45 45.72,57.78 arc-62 42.55,87.63 arc-49 53.34,103.5 arc-50 75.56,111.76
  pour Top (isolate 0.813, hatched): 8.89,43.18 43.18,43.18 43.18,8.89 109.22,8.89 109.22,43.18 143.51,43.18 143.51,109.22 109.22,109.22 109.22,143.51 43.18,143.51 43.18,109.22 8.89,109.22
VDD
  Bottom 0.61: D2.C 49.96,75.34 P4ZD3.C 51.3,70.42 C3.+ 57.15,62.09 C1.2 58.92,58.42 62.23,58.42 | 62.23,58.42 63.5,59.69 63.98,60.8 PH1.1 | U$1.P$2 62.87,50.8 62.23,51.44 62.23,58.42
VSS
  Bottom 0.61: C5.1 87,46.23 87,47.62 86.79,47.83 P4ZD1.A 87,50.59 87,50.8 84.45,50.8 | B1.- 61.56,93.38 59.69,95.25 52.07,95.25 50.16,92.08 C9.- 47.2,77.41 P4ZD3.A 47.13,70.55 C3.- 49.67,60.82 54.61,54.61 57.02,54.61 C1.1 57.15,50.8 arc41 73.03,44.45 73.03,50.8 U$1.P$7 78.89,50.8 R1.2 84.45,50.8 | 84.45,50.8 82.55,55.56 80.01,55.56 80.01,65.41 76.2,65.41 OK1.2
(copper drawn outside any net)
  shapes: Bottom circle x1

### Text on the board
Top: MICHAELS | 26112011
Bottom: MICHAELS | 26112011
